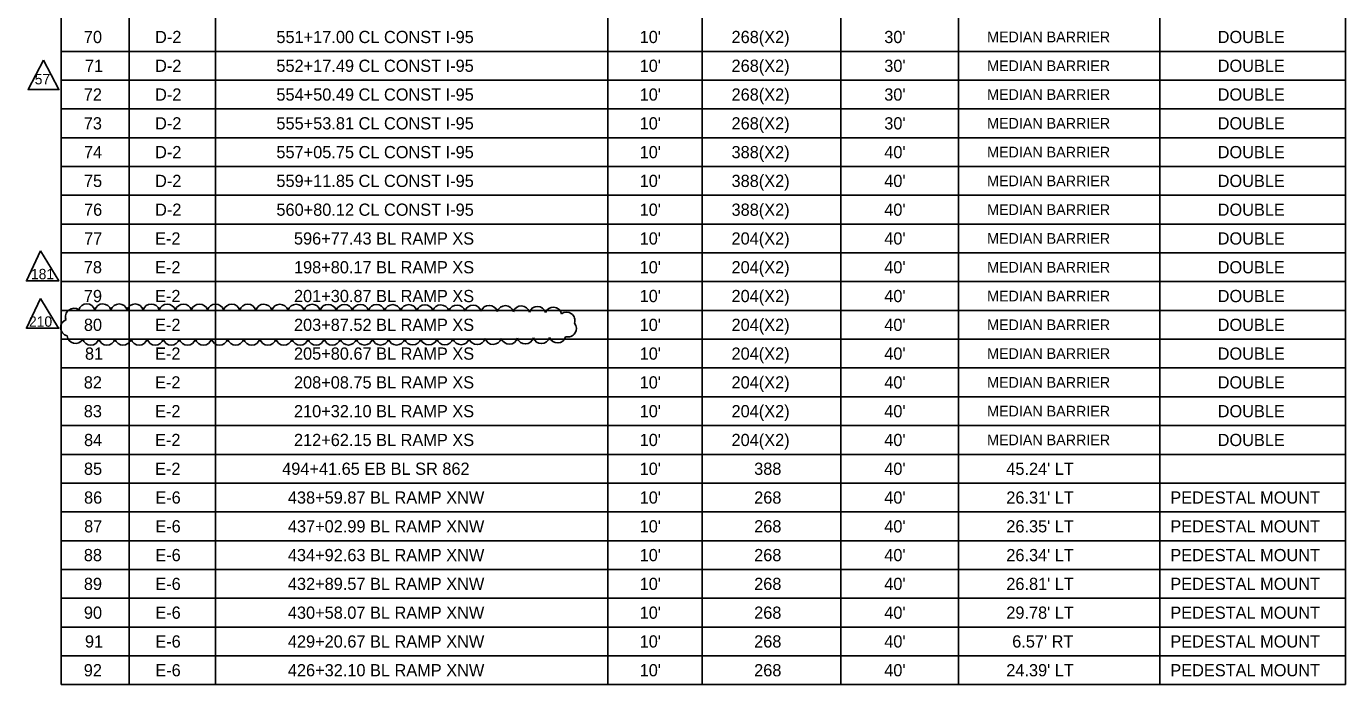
# Model space of a CAD drawing. Extents: x -818.1 to -802.4, y -2221.2 to -2187.7.
# Drawn here: x -809.93 to -802.37, y -2195.94 to -2192.17 of the extents above; entities that cross this region are included whole.
import ezdxf

# ---------------------------------------------------------------- set-up
doc = ezdxf.new("R2010")
doc.units = 0
for name, color, linetype in [('Cloud_dp', 7, 'Continuous'), ('SumBoxBorder_dp', 7, 'Continuous'), ('SumBoxLines_dp', 7, 'Continuous'), ('SumBoxLinesMin_dp', 7, 'Continuous'), ('TextLabel', 7, 'Continuous')]:
    doc.layers.add(name, color=color, linetype=linetype)

msp = doc.modelspace()

# ---------------------------------------------------------------- linework, layer by layer
at = {"layer": 'Cloud_dp'}
for points in [[(-809.8352, -2192.3616), (-809.9232, -2192.5312), (-809.7472, -2192.5312)], [(-809.852, -2193.4556), (-809.933, -2193.6272), (-809.7481, -2193.6272)], [(-809.8525, -2193.7282), (-809.9333, -2193.8994), (-809.7489, -2193.8994)]]:
    msp.add_lwpolyline(points, close=True, dxfattribs=at)
for centre, start, end in [((-809.5869, -2193.8077), 17.44459, 162.44459), ((-809.4946, -2193.8078), 17.38723, 162.38723), ((-809.4023, -2193.808), 17.38723, 162.38723), ((-809.31, -2193.8082), 17.38723, 162.38723), ((-809.2177, -2193.8084), 17.38723, 162.38723), ((-809.1254, -2193.8086), 17.38723, 162.38723), ((-809.0331, -2193.8087), 17.38723, 162.38723), ((-808.9408, -2193.8089), 17.38723, 162.38723), ((-808.8485, -2193.8091), 17.38723, 162.38723), ((-808.7562, -2193.8093), 17.38723, 162.38723), ((-808.6639, -2193.8095), 17.38723, 162.38723), ((-808.5716, -2193.8097), 17.38723, 162.38723), ((-808.4794, -2193.8098), 17.38723, 162.38723), ((-808.3871, -2193.81), 17.38723, 162.38723), ((-808.2948, -2193.8102), 17.38701, 162.38701), ((-808.2025, -2193.8104), 17.37001, 162.37001), ((-808.1102, -2193.8106), 17.3403, 162.3403), ((-808.0179, -2193.8109), 17.30711, 162.30711), ((-807.9256, -2193.8113), 17.2697, 162.2697), ((-807.8333, -2193.8117), 17.22708, 162.22708), ((-807.741, -2193.8121), 17.17794, 162.17794), ((-807.6487, -2193.8127), 17.1204, 162.1204), ((-807.5565, -2193.8134), 17.05177, 162.05177), ((-807.4642, -2193.8142), 16.96794, 161.96794), ((-807.3719, -2193.8151), 16.86232, 161.86232), ((-807.2797, -2193.8162), 16.72341, 161.72341), ((-807.1874, -2193.8176), 16.52891, 161.52891), ((-807.0952, -2193.8195), 16.22738, 161.22738), ((-809.6606, -2193.8329), 55.25371, 200.25371), ((-807.0031, -2193.822), 15.65718, 160.65718), ((-806.9115, -2193.8268), 13.36526, 158.36526), ((-806.836, -2193.8547), 341.03892, 126.03892), ((-809.6886, -2193.8948), 111.0484, 256.0484), ((-806.8279, -2193.9007), 253.81443, 38.81443), ((-809.6521, -2193.9375), 185.06988, 330.06988), ((-809.564, -2193.9471), 197.5, 342.5), ((-809.4717, -2193.9471), 197.5, 342.5), ((-809.3794, -2193.9471), 197.5, 342.5), ((-809.2871, -2193.9471), 197.5, 342.5), ((-809.1948, -2193.9471), 197.5, 342.5), ((-809.1025, -2193.9471), 197.5, 342.5), ((-809.0102, -2193.9471), 197.5, 342.5), ((-808.9179, -2193.9471), 197.5, 342.5), ((-808.8256, -2193.9471), 197.5, 342.5), ((-808.7333, -2193.9471), 197.5, 342.5), ((-808.641, -2193.9471), 197.5, 342.5), ((-808.5487, -2193.9471), 197.5, 342.5), ((-808.4564, -2193.9471), 197.5, 342.5), ((-808.3642, -2193.9471), 197.5, 342.5), ((-808.2719, -2193.9471), 197.5, 342.5), ((-808.1796, -2193.9471), 197.50223, 342.50223), ((-808.0873, -2193.947), 197.5285, 342.5285), ((-807.995, -2193.947), 197.56426, 342.56426), ((-807.9027, -2193.9468), 197.60438, 342.60438), ((-807.8104, -2193.9466), 197.64984, 342.64984), ((-807.7181, -2193.9463), 197.70193, 342.70193), ((-807.6258, -2193.946), 197.76245, 342.76245), ((-807.5336, -2193.9455), 197.83394, 342.83394), ((-807.4413, -2193.9449), 197.92019, 342.92019), ((-807.349, -2193.9441), 198.02709, 343.02709), ((-807.2568, -2193.9431), 198.16451, 343.16451), ((-807.1645, -2193.9419), 198.35049, 343.35049), ((-807.0723, -2193.9403), 198.62289, 343.62289), ((-806.9802, -2193.9382), 199.08108, 344.08108), ((-806.8882, -2193.9348), 200.14914, 345.14914)]:
    msp.add_arc(centre, 0.0484, start, end, dxfattribs=at)
at = {"layer": 'SumBoxBorder_dp'}
for p, q in [((-809.7339, -2187.6917), (-809.7339, -2195.9417)), ((-802.3689, -2187.6917), (-802.3689, -2195.9417)), ((-809.7339, -2195.9417), (-806.5989, -2195.9417)), ((-806.5989, -2195.9417), (-802.3689, -2195.9417)), ((-806.0589, -2195.9417), (-803.4339, -2195.9417))]:
    msp.add_line(p, q, dxfattribs=at)
at = {"layer": 'SumBoxLines_dp'}
for p, q in [((-809.3439, -2188.0217), (-809.3439, -2195.9417)), ((-809.3439, -2188.0217), (-809.3439, -2195.9417)), ((-808.8489, -2188.0217), (-808.8489, -2195.9417)), ((-808.8489, -2188.0217), (-808.8489, -2195.9417)), ((-806.5989, -2188.0217), (-806.5989, -2195.9417)), ((-806.0589, -2188.0217), (-806.0589, -2195.9417)), ((-806.0589, -2188.0217), (-806.0589, -2195.9417)), ((-805.2639, -2188.0217), (-805.2639, -2195.9417)), ((-805.2639, -2188.0217), (-805.2639, -2195.9417)), ((-804.5889, -2188.0217), (-804.5889, -2195.9417)), ((-804.5889, -2188.0217), (-804.5889, -2195.9417)), ((-803.4339, -2188.0217), (-803.4339, -2195.9417)), ((-803.4339, -2188.0217), (-803.4339, -2195.9417)), ((-806.5989, -2192.3117), (-806.5989, -2195.6117)), ((-806.5989, -2195.7767), (-806.5989, -2195.9417))]:
    msp.add_line(p, q, dxfattribs=at)
at = {"layer": 'SumBoxLinesMin_dp'}
for p, q in [((-809.7339, -2192.3117), (-808.8489, -2192.3117)), ((-809.7339, -2192.3117), (-802.3689, -2192.3117)), ((-806.5989, -2192.3117), (-802.3689, -2192.3117)), ((-809.7339, -2192.4767), (-802.3689, -2192.4767)), ((-809.7339, -2192.4767), (-802.3689, -2192.4767)), ((-809.7339, -2192.6417), (-802.3689, -2192.6417)), ((-809.7339, -2192.6417), (-802.3689, -2192.6417)), ((-809.7339, -2192.8067), (-808.8489, -2192.8067)), ((-809.7339, -2192.8067), (-802.3689, -2192.8067)), ((-806.5989, -2192.8067), (-802.3689, -2192.8067)), ((-809.7339, -2192.9717), (-802.3689, -2192.9717)), ((-809.7339, -2192.9717), (-802.3689, -2192.9717)), ((-809.7339, -2193.1367), (-808.8489, -2193.1367)), ((-809.7339, -2193.1367), (-802.3689, -2193.1367)), ((-806.5989, -2193.1367), (-802.3689, -2193.1367)), ((-809.7339, -2193.3017), (-802.3689, -2193.3017)), ((-809.7339, -2193.3017), (-802.3689, -2193.3017)), ((-809.7339, -2193.4667), (-802.3689, -2193.4667)), ((-809.7339, -2193.4667), (-802.3689, -2193.4667)), ((-809.7339, -2193.6317), (-802.3689, -2193.6317)), ((-809.7339, -2193.6317), (-802.3689, -2193.6317)), ((-809.7339, -2193.7967), (-802.3689, -2193.7967)), ((-809.7339, -2193.7967), (-802.3689, -2193.7967)), ((-809.7339, -2193.9617), (-802.3689, -2193.9617)), ((-809.7339, -2193.9617), (-802.3689, -2193.9617)), ((-809.7339, -2194.1267), (-808.8489, -2194.1267)), ((-809.7339, -2194.1267), (-802.3689, -2194.1267)), ((-806.5989, -2194.1267), (-802.3689, -2194.1267)), ((-809.7339, -2194.2917), (-808.8489, -2194.2917)), ((-809.7339, -2194.2917), (-802.3689, -2194.2917)), ((-806.5989, -2194.2917), (-802.3689, -2194.2917)), ((-809.7339, -2194.4567), (-808.8489, -2194.4567)), ((-809.7339, -2194.4567), (-802.3689, -2194.4567)), ((-806.5989, -2194.4567), (-802.3689, -2194.4567)), ((-809.7339, -2194.6217), (-808.8489, -2194.6217)), ((-809.7339, -2194.6217), (-802.3689, -2194.6217)), ((-806.5989, -2194.6217), (-802.3689, -2194.6217)), ((-809.7339, -2194.7867), (-804.5889, -2194.7867)), ((-809.7339, -2194.7867), (-802.3689, -2194.7867)), ((-803.4339, -2194.7867), (-802.3689, -2194.7867)), ((-809.7339, -2194.9517), (-802.3689, -2194.9517)), ((-809.3439, -2194.9517), (-808.8489, -2194.9517)), ((-806.5989, -2194.9517), (-804.5889, -2194.9517)), ((-803.4339, -2194.9517), (-802.3689, -2194.9517)), ((-809.7339, -2195.1167), (-808.8489, -2195.1167)), ((-809.7339, -2195.1167), (-802.3689, -2195.1167)), ((-806.5989, -2195.1167), (-804.5889, -2195.1167)), ((-803.4339, -2195.1167), (-802.3689, -2195.1167)), ((-809.7339, -2195.2817), (-802.3689, -2195.2817)), ((-809.7339, -2195.2817), (-802.3689, -2195.2817)), ((-809.7339, -2195.4467), (-802.3689, -2195.4467)), ((-809.7339, -2195.4467), (-802.3689, -2195.4467)), ((-809.7339, -2195.6117), (-802.3689, -2195.6117)), ((-809.7339, -2195.6117), (-802.3689, -2195.6117)), ((-809.7339, -2195.7767), (-808.8489, -2195.7767)), ((-809.7339, -2195.7767), (-802.3689, -2195.7767)), ((-806.5989, -2195.7767), (-802.3689, -2195.7767)), ((-803.4339, -2195.9417), (-802.3689, -2195.9417))]:
    msp.add_line(p, q, dxfattribs=at)

# ---------------------------------------------------------------- texts
at = {"layer": 'Cloud_dp'}
for s, height, p in [('57', 0.06, (-809.8859, -2192.501)), ('181', 0.05952, (-809.9071, -2193.6181)), ('210', 0.05938, (-809.9183, -2193.8902))]:
    msp.add_text(s, height=height, dxfattribs=at).set_placement(p)
at = {"layer": 'TextLabel'}
for s, height, p in [('70', 0.07, (-809.6036, -2192.2642)), ('D-2', 0.07, (-809.1955, -2192.2642)), ('551+17.00 CL CONST I-95', 0.07, (-808.4997, -2192.2642)), ("10'", 0.07, (-806.4168, -2192.2642)), ('268(X2)', 0.07, (-805.8899, -2192.2642)), ("30'", 0.07, (-805.0143, -2192.2642)), ('MEDIAN BARRIER', 0.06125, (-804.4245, -2192.2598)), ('DOUBLE', 0.07, (-803.1024, -2192.2642)), ('71', 0.07, (-809.5974, -2192.4292)), ('D-2', 0.07, (-809.1955, -2192.4292)), ('552+17.49 CL CONST I-95', 0.07, (-808.4997, -2192.4292)), ("10'", 0.07, (-806.4168, -2192.4292)), ('268(X2)', 0.07, (-805.8899, -2192.4292)), ("30'", 0.07, (-805.0143, -2192.4292)), ('MEDIAN BARRIER', 0.06125, (-804.4245, -2192.4248)), ('DOUBLE', 0.07, (-803.1024, -2192.4292)), ('72', 0.07, (-809.6042, -2192.5942)), ('D-2', 0.07, (-809.1955, -2192.5942)), ('554+50.49 CL CONST I-95', 0.07, (-808.4997, -2192.5942)), ("10'", 0.07, (-806.4168, -2192.5942)), ('268(X2)', 0.07, (-805.8899, -2192.5942)), ("30'", 0.07, (-805.0143, -2192.5942)), ('MEDIAN BARRIER', 0.06125, (-804.4245, -2192.5898)), ('DOUBLE', 0.07, (-803.1024, -2192.5942)), ('73', 0.07, (-809.6042, -2192.7592)), ('D-2', 0.07, (-809.1955, -2192.7592)), ('555+53.81 CL CONST I-95', 0.07, (-808.4997, -2192.7592)), ("10'", 0.07, (-806.4168, -2192.7592)), ('268(X2)', 0.07, (-805.8899, -2192.7592)), ("30'", 0.07, (-805.0143, -2192.7592)), ('MEDIAN BARRIER', 0.06125, (-804.4245, -2192.7548)), ('DOUBLE', 0.07, (-803.1024, -2192.7592)), ('74', 0.07, (-809.6028, -2192.9242)), ('D-2', 0.07, (-809.1955, -2192.9242)), ('557+05.75 CL CONST I-95', 0.07, (-808.4997, -2192.9242)), ("10'", 0.07, (-806.4168, -2192.9242)), ('388(X2)', 0.07, (-805.8899, -2192.9242)), ("40'", 0.07, (-805.0143, -2192.9242)), ('MEDIAN BARRIER', 0.06125, (-804.4245, -2192.9198)), ('DOUBLE', 0.07, (-803.1024, -2192.9242)), ('388(X2)', 0.07, (-805.8899, -2193.0892)), ('75', 0.07, (-809.6033, -2193.0892)), ('D-2', 0.07, (-809.1955, -2193.0892)), ('559+11.85 CL CONST I-95', 0.07, (-808.4997, -2193.0892)), ("10'", 0.07, (-806.4168, -2193.0892)), ("40'", 0.07, (-805.0143, -2193.0892)), ('MEDIAN BARRIER', 0.06125, (-804.4245, -2193.0848)), ('DOUBLE', 0.07, (-803.1024, -2193.0892)), ('76', 0.07, (-809.6028, -2193.2542)), ('D-2', 0.07, (-809.1955, -2193.2542)), ('560+80.12 CL CONST I-95', 0.07, (-808.4997, -2193.2542)), ("10'", 0.07, (-806.4168, -2193.2542)), ('388(X2)', 0.07, (-805.8899, -2193.2542)), ("40'", 0.07, (-805.0143, -2193.2542)), ('MEDIAN BARRIER', 0.06125, (-804.4245, -2193.2498)), ('DOUBLE', 0.07, (-803.1024, -2193.2542)), ('77', 0.07, (-809.6022, -2193.4192)), ('E-2', 0.07, (-809.1955, -2193.4192)), ('596+77.43 BL RAMP XS', 0.07, (-808.399, -2193.4192)), ("10'", 0.07, (-806.4168, -2193.4192)), ('204(X2)', 0.07, (-805.8899, -2193.4192)), ("40'", 0.07, (-805.0143, -2193.4192)), ('MEDIAN BARRIER', 0.06125, (-804.4245, -2193.4148)), ('DOUBLE', 0.07, (-803.1024, -2193.4192)), ('78', 0.07, (-809.6039, -2193.5842)), ('E-2', 0.07, (-809.1955, -2193.5842)), ('198+80.17 BL RAMP XS', 0.07, (-808.399, -2193.5842)), ("10'", 0.07, (-806.4168, -2193.5842)), ('204(X2)', 0.07, (-805.8899, -2193.5842)), ("40'", 0.07, (-805.0143, -2193.5842)), ('MEDIAN BARRIER', 0.06125, (-804.4245, -2193.5798)), ('DOUBLE', 0.07, (-803.1024, -2193.5842)), ('79', 0.07, (-809.6038, -2193.7492)), ('E-2', 0.07, (-809.1955, -2193.7492)), ('201+30.87 BL RAMP XS', 0.07, (-808.399, -2193.7492)), ("10'", 0.07, (-806.4168, -2193.7492)), ('204(X2)', 0.07, (-805.8899, -2193.7492)), ("40'", 0.07, (-805.0143, -2193.7492)), ('MEDIAN BARRIER', 0.06125, (-804.4245, -2193.7448)), ('DOUBLE', 0.07, (-803.1024, -2193.7492)), ('80', 0.07, (-809.6036, -2193.9142)), ('E-2', 0.07, (-809.1955, -2193.9142)), ('203+87.52 BL RAMP XS', 0.07, (-808.399, -2193.9142)), ("10'", 0.07, (-806.4168, -2193.9142)), ('204(X2)', 0.07, (-805.8899, -2193.9142)), ("40'", 0.07, (-805.0143, -2193.9142)), ('MEDIAN BARRIER', 0.06125, (-804.4245, -2193.9098)), ('DOUBLE', 0.07, (-803.1024, -2193.9142)), ('81', 0.07, (-809.5974, -2194.0792)), ('E-2', 0.07, (-809.1955, -2194.0792)), ('205+80.67 BL RAMP XS', 0.07, (-808.399, -2194.0792)), ("10'", 0.07, (-806.4168, -2194.0792)), ('204(X2)', 0.07, (-805.8899, -2194.0792)), ("40'", 0.07, (-805.0143, -2194.0792)), ('MEDIAN BARRIER', 0.06125, (-804.4245, -2194.0748)), ('DOUBLE', 0.07, (-803.1024, -2194.0792)), ('82', 0.07, (-809.6042, -2194.2442)), ('E-2', 0.07, (-809.1955, -2194.2442)), ('208+08.75 BL RAMP XS', 0.07, (-808.399, -2194.2442)), ("10'", 0.07, (-806.4168, -2194.2442)), ('204(X2)', 0.07, (-805.8899, -2194.2442)), ("40'", 0.07, (-805.0143, -2194.2442)), ('MEDIAN BARRIER', 0.06125, (-804.4245, -2194.2398)), ('DOUBLE', 0.07, (-803.1024, -2194.2442)), ('83', 0.07, (-809.6042, -2194.4092)), ('E-2', 0.07, (-809.1955, -2194.4092)), ('210+32.10 BL RAMP XS', 0.07, (-808.399, -2194.4092)), ("10'", 0.07, (-806.4168, -2194.4092)), ('204(X2)', 0.07, (-805.8899, -2194.4092)), ("40'", 0.07, (-805.0143, -2194.4092)), ('MEDIAN BARRIER', 0.06125, (-804.4245, -2194.4048)), ('DOUBLE', 0.07, (-803.1024, -2194.4092)), ('84', 0.07, (-809.6028, -2194.5742)), ('E-2', 0.07, (-809.1955, -2194.5742)), ('212+62.15 BL RAMP XS', 0.07, (-808.399, -2194.5742)), ("10'", 0.07, (-806.4168, -2194.5742)), ('204(X2)', 0.07, (-805.8899, -2194.5742)), ("40'", 0.07, (-805.0143, -2194.5742)), ('MEDIAN BARRIER', 0.06125, (-804.4245, -2194.5698)), ('DOUBLE', 0.07, (-803.1024, -2194.5742)), ('85', 0.07, (-809.6033, -2194.7392)), ('E-2', 0.07, (-809.1955, -2194.7392)), ('494+41.65 EB BL SR 862', 0.07, (-808.4667, -2194.7392)), ("10'", 0.07, (-806.4168, -2194.7392)), ('388', 0.07, (-805.7603, -2194.7392)), ("40'", 0.07, (-805.0143, -2194.7392)), ("45.24' LT", 0.07, (-804.3145, -2194.7392)), ('86', 0.07, (-809.6028, -2194.9042)), ('E-6', 0.07, (-809.1941, -2194.9042)), ('438+59.87 BL RAMP XNW', 0.07, (-808.434, -2194.9042)), ("10'", 0.07, (-806.4168, -2194.9042)), ('268', 0.07, (-805.7603, -2194.9042)), ("40'", 0.07, (-805.0143, -2194.9042)), ("26.31' LT", 0.07, (-804.3145, -2194.9042)), ('PEDESTAL MOUNT', 0.07, (-803.3739, -2194.9042)), ('87', 0.07, (-809.6022, -2195.0692)), ('E-6', 0.07, (-809.1941, -2195.0692)), ('437+02.99 BL RAMP XNW', 0.07, (-808.434, -2195.0692)), ("10'", 0.07, (-806.4168, -2195.0692)), ('268', 0.07, (-805.7603, -2195.0692)), ("40'", 0.07, (-805.0143, -2195.0692)), ("26.35' LT", 0.07, (-804.3145, -2195.0692)), ('PEDESTAL MOUNT', 0.07, (-803.3739, -2195.0692)), ('88', 0.07, (-809.6039, -2195.2342)), ('E-6', 0.07, (-809.1941, -2195.2342)), ('434+92.63 BL RAMP XNW', 0.07, (-808.434, -2195.2342)), ("10'", 0.07, (-806.4168, -2195.2342)), ('268', 0.07, (-805.7603, -2195.2342)), ("40'", 0.07, (-805.0143, -2195.2342)), ("26.34' LT", 0.07, (-804.3145, -2195.2342)), ('PEDESTAL MOUNT', 0.07, (-803.3739, -2195.2342)), ('89', 0.07, (-809.6038, -2195.3992)), ('E-6', 0.07, (-809.1941, -2195.3992)), ('432+89.57 BL RAMP XNW', 0.07, (-808.434, -2195.3992)), ("10'", 0.07, (-806.4168, -2195.3992)), ('268', 0.07, (-805.7603, -2195.3992)), ("40'", 0.07, (-805.0143, -2195.3992)), ("26.81' LT", 0.07, (-804.3145, -2195.3992)), ('PEDESTAL MOUNT', 0.07, (-803.3739, -2195.3992)), ('90', 0.07, (-809.6036, -2195.5642)), ('E-6', 0.07, (-809.1941, -2195.5642)), ('430+58.07 BL RAMP XNW', 0.07, (-808.434, -2195.5642)), ("10'", 0.07, (-806.4168, -2195.5642)), ('268', 0.07, (-805.7603, -2195.5642)), ("40'", 0.07, (-805.0143, -2195.5642)), ("29.78' LT", 0.07, (-804.3145, -2195.5642)), ('PEDESTAL MOUNT', 0.07, (-803.3739, -2195.5642)), ('91', 0.07, (-809.5974, -2195.7292)), ('E-6', 0.07, (-809.1941, -2195.7292)), ('429+20.67 BL RAMP XNW', 0.07, (-808.434, -2195.7292)), ("10'", 0.07, (-806.4168, -2195.7292)), ('268', 0.07, (-805.7603, -2195.7292)), ("40'", 0.07, (-805.0143, -2195.7292)), ("6.57' RT", 0.07, (-804.2806, -2195.7292)), ('PEDESTAL MOUNT', 0.07, (-803.3739, -2195.7292)), ('92', 0.07, (-809.6042, -2195.8942)), ('E-6', 0.07, (-809.1941, -2195.8942)), ('426+32.10 BL RAMP XNW', 0.07, (-808.434, -2195.8942)), ("10'", 0.07, (-806.4168, -2195.8942)), ('268', 0.07, (-805.7603, -2195.8942)), ("40'", 0.07, (-805.0143, -2195.8942)), ("24.39' LT", 0.07, (-804.3145, -2195.8942)), ('PEDESTAL MOUNT', 0.07, (-803.3739, -2195.8942))]:
    msp.add_text(s, height=height, dxfattribs=at).set_placement(p)

doc.saveas('drawing.dxf')
